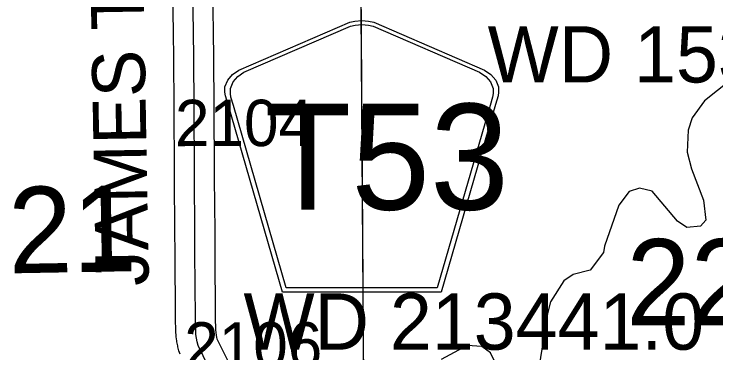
# Model space of a CAD drawing. Extents: x 23.6 to 68.7, y -63 to -29.
# Drawn here: x 41.265 to 42.324, y -55.315 to -54.804 of the extents above; entities that cross this region are included whole.
import ezdxf

# ---------------------------------------------------------------- set-up
doc = ezdxf.new("R2010")
doc.units = 0
for name, color, linetype in [('tdCoHydroRiver', 7, 'Continuous'), ('tdCoSecRdNmbr', 7, 'Continuous'), ('tdCoSecRdTxt', 7, 'Continuous'), ('tdCoSecRteBand', 7, 'Continuous'), ('tdCoSecRteCL', 7, 'Continuous'), ('tdCoSectLine', 7, 'Continuous'), ('tdCoSectLinePart', 7, 'Continuous'), ('tdCoSectNmbr', 7, 'Continuous'), ('tdCoShieldCoRte', 7, 'Continuous'), ('tdCoStrucSecCoName', 7, 'Continuous'), ('tdCoSurfGravel', 7, 'Continuous')]:
    doc.layers.add(name, color=color, linetype=linetype)

msp = doc.modelspace()

# ---------------------------------------------------------------- linework, layer by layer
at = {"layer": 'tdCoHydroRiver'}
for points in [[(42.3629, -54.8899), (42.3065, -54.9346), (42.2878, -54.9601), (42.2817, -54.9791), (42.2804, -55.0122), (42.2869, -55.0374), (42.3048, -55.0846), (42.3082, -55.1146), (42.3004, -55.1241), (42.2799, -55.1259), (42.2656, -55.1165), (42.2273, -55.0711), (42.2083, -55.0666), (42.1926, -55.0715), (42.177, -55.0921), (42.1554, -55.1539), (42.154, -55.1634), (42.1337, -55.1904), (42.1085, -55.197), (42.0944, -55.2066), (42.0742, -55.2383), (42.0696, -55.2557), (42.0577, -55.3316)], [(41.9898, -55.3275), (41.9833, -55.315), (41.9706, -55.3056), (41.9485, -55.3043), (41.9092, -55.3252)]]:
    msp.add_lwpolyline(points, dxfattribs=at)
at = {"layer": 'tdCoSecRteBand'}
for points in [[(41.5155, -55.3174), (41.5142, -55.3147), (41.5135, -55.3119), (41.512, -55.3063), (41.5118, -55.3053), (41.5116, -55.3044), (41.5105, -55.2987), (41.5103, -55.2978), (41.5102, -55.2968), (41.5095, -55.2911), (41.5094, -55.2901), (41.5093, -55.2892), (41.509, -55.2834), (41.5089, -55.2829), (41.5089, -55.2824), (41.5084, -55.2633), (41.5084, -55.263), (41.5084, -55.2627), (41.5077, -55.1639), (41.5075, -55.1322), (41.5068, -55.0517), (41.5068, -55.0516), (41.5068, -55.0516), (41.5063, -54.9355), (41.5053, -54.8227), (41.5048, -54.8093), (41.5048, -54.8089), (41.5048, -54.8085), (41.5043, -54.7332)], [(41.5643, -54.7321), (41.5648, -54.8076), (41.5653, -54.821), (41.5653, -54.8214), (41.5653, -54.8218), (41.5663, -54.9351), (41.5663, -54.9352), (41.5663, -54.9352), (41.5668, -55.0512), (41.5675, -55.1317), (41.5677, -55.1634), (41.5677, -55.1635), (41.5677, -55.1635), (41.5684, -55.262), (41.5689, -55.2803), (41.5691, -55.2845), (41.5696, -55.2883), (41.5703, -55.2921), (41.5708, -55.2938), (41.5926, -55.3384)]]:
    msp.add_lwpolyline(points, dxfattribs=at)
at = {"layer": 'tdCoSecRteCL'}
msp.add_lwpolyline([(41.6027, -55.4258), (41.5969, -55.4147), (41.5827, -55.3854), (41.5657, -55.3518), (41.5425, -55.3043), (41.5411, -55.2987), (41.54, -55.2931), (41.5392, -55.2873), (41.5389, -55.2816), (41.5384, -55.2625), (41.5377, -55.1637), (41.5375, -55.132), (41.5368, -55.0514), (41.5363, -54.9354), (41.5353, -54.8221), (41.5348, -54.8083), (41.5343, -54.7323), (41.5317, -54.6811), (41.53, -54.6573)], dxfattribs=at)
at = {"layer": 'tdCoSectLine'}
msp.add_lwpolyline([(41.787, -54.6536), (41.7942, -55.6609)], dxfattribs=at)
at = {"layer": 'tdCoSectLinePart'}
msp.add_lwpolyline([(41.7872, -54.6832), (41.7926, -55.4377)], dxfattribs=at)
at = {"layer": 'tdCoShieldCoRte'}
for points in [[(41.6696, -55.2233), (41.5876, -54.9404), (41.5837, -54.9272), (41.583, -54.9214), (41.583, -54.9135), (41.5873, -54.9032), (41.5945, -54.8947), (41.6041, -54.8881), (41.7714, -54.8157), (41.7789, -54.8141), (41.7893, -54.8132), (41.7997, -54.8141), (41.8073, -54.8157), (41.9745, -54.8881), (41.9841, -54.8947), (41.9914, -54.9032), (41.9956, -54.9135), (41.9956, -54.9214), (41.9949, -54.9272), (41.991, -54.9404), (41.9091, -55.2233)], [(41.6754, -55.217), (41.5957, -54.9417), (41.592, -54.9291), (41.5913, -54.9234), (41.5913, -54.9159), (41.5953, -54.906), (41.6023, -54.8979), (41.6115, -54.8915), (41.7721, -54.822), (41.7793, -54.8204), (41.7893, -54.8196), (41.7993, -54.8204), (41.8065, -54.822), (41.9671, -54.8915), (41.9763, -54.8979), (41.9833, -54.906), (41.9874, -54.9159), (41.9874, -54.9234), (41.9867, -54.9291), (41.9829, -54.9417), (41.9032, -55.217)]]:
    msp.add_lwpolyline(points, close=True, dxfattribs=at)
at = {"layer": 'tdCoSurfGravel'}
for points in [[(41.5375, -55.132), (41.5368, -55.0514), (41.5363, -54.9354), (41.5353, -54.8221), (41.5348, -54.8083), (41.5343, -54.7323), (41.5317, -54.6811), (41.53, -54.6573)], [(41.6027, -55.4258), (41.5969, -55.4147), (41.5827, -55.3854), (41.5657, -55.3518), (41.5425, -55.3043), (41.5411, -55.2987), (41.54, -55.2931), (41.5392, -55.2873), (41.5389, -55.2816), (41.5384, -55.2625), (41.5377, -55.1637), (41.5375, -55.132)]]:
    msp.add_lwpolyline(points, dxfattribs=at)

# ---------------------------------------------------------------- texts
at = {"layer": 'tdCoSecRdNmbr'}
for s, p in [('2104', (41.5076, -55.0031)), ('2106', (41.5215, -55.339))]:
    msp.add_text(s, height=0.07, rotation=0.0324, dxfattribs=at).set_placement(p)
at = {"layer": 'tdCoSecRdTxt'}
msp.add_text('JAMES TR', height=0.08, rotation=91, dxfattribs=at).set_placement((41.4682, -55.2137))
at = {"layer": 'tdCoSectNmbr'}
msp.add_text('21', height=0.13, rotation=1.0321, dxfattribs=at).set_placement((41.2571, -55.1952))
msp.add_text('22', height=0.13, dxfattribs=at).set_placement((42.1885, -55.2734))
at = {"layer": 'tdCoShieldCoRte'}
msp.add_text('T53', height=0.16, dxfattribs=at).set_placement((41.6427, -55.099))
at = {"layer": 'tdCoStrucSecCoName'}
for s, p in [('WD 153383.5', (41.9792, -54.9069)), ('WD 213441.0', (41.6109, -55.3104))]:
    msp.add_text(s, height=0.085, dxfattribs=at).set_placement(p)

doc.saveas('drawing.dxf')
